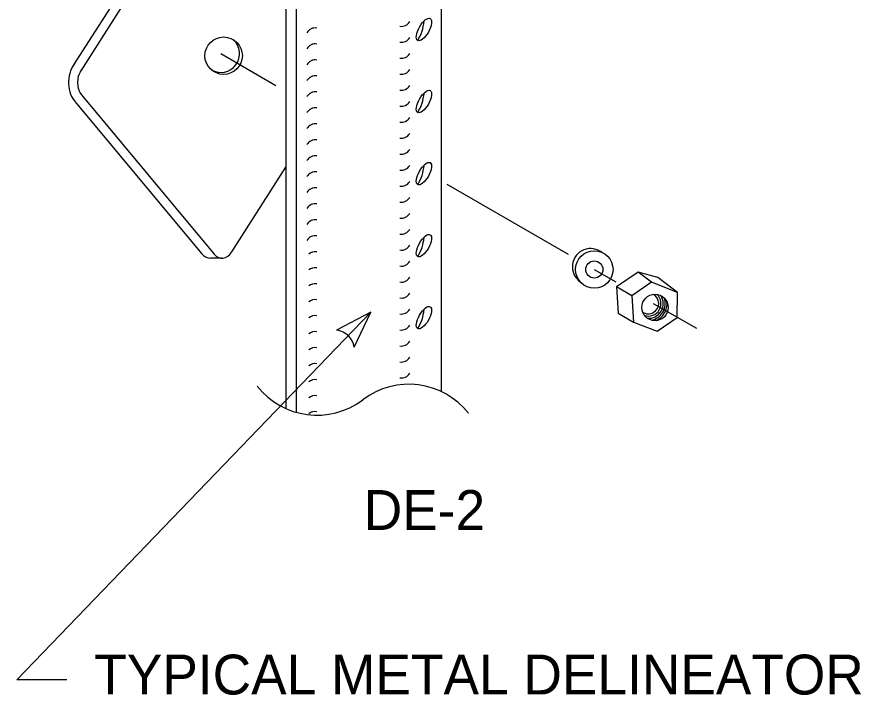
# Model space of a CAD drawing. Extents: x -0.14 to 2.7, y -0.05 to 1.78.
# Drawn here: x 0.5622 to 0.7392, y 1.3134 to 1.4552 of the extents above; entities that cross this region are included whole.
import ezdxf

# ---------------------------------------------------------------- set-up
doc = ezdxf.new("R2010")
doc.units = 0
doc.layers.add('CT_CSHT_GeneralLabel', color=7, linetype='Continuous')

msp = doc.modelspace()

# ---------------------------------------------------------------- linework, layer by layer
at = {"layer": 'CT_CSHT_GeneralLabel'}
for p, q in [((0.6509403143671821, 1.5261712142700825), (0.6509403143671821, 1.3768578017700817)), ((0.6184386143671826, 1.5115208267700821), (0.6184386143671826, 1.3733004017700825)), ((0.6206105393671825, 1.5115208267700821), (0.6206105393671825, 1.3725139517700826)), ((0.5988637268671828, 1.4840998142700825), (0.5740299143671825, 1.4451337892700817)), ((0.6010852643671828, 1.4840226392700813), (0.5755458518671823, 1.4439449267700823)), ((0.604841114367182, 1.4475023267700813), (0.6163475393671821, 1.4408560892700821)), ((0.5757002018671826, 1.4388715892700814), (0.6034501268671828, 1.4055742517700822)), ((0.5743257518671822, 1.4374622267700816), (0.600782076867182, 1.4057120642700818)), ((0.607132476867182, 1.4060428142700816), (0.6184386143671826, 1.4237875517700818)), ((0.6776079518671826, 1.4054823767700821), (0.652197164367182, 1.4201566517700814)), ((0.6050634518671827, 1.4047124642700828), (0.602720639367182, 1.404752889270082)), ((0.6829863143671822, 1.402378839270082), (0.6874845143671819, 1.3997806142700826)), ((0.6921921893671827, 1.4018239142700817), (0.6876076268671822, 1.398746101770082)), ((0.6962493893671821, 1.4006865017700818), (0.6921921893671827, 1.4018239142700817)), ((0.6949337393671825, 1.3997218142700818), (0.6921921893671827, 1.4018239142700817)), ((0.700367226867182, 1.3975407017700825), (0.6962493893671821, 1.4006865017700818)), ((0.6876076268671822, 1.398746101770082), (0.6879824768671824, 1.3932354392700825)), ((0.6908250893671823, 1.3968920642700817), (0.6876076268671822, 1.398746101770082)), ((0.704398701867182, 1.3900124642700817), (0.6954004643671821, 1.3952070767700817)), ((0.6362552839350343, 1.3934313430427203), (0.6290729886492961, 1.389674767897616)), ((0.6327633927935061, 1.386116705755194), (0.6362552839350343, 1.3934313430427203)), ((0.6879824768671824, 1.3932354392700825), (0.6911962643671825, 1.3913795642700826)), ((0.6327633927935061, 1.386116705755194), (0.6327633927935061, 1.386116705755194))]:
    msp.add_line(p, q, dxfattribs=at)
msp.add_lwpolyline([(0.6949337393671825, 1.3997218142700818), (0.6908250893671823, 1.3968920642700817), (0.6911962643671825, 1.3913795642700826), (0.6961299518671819, 1.3895108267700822), (0.7003415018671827, 1.3923387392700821), (0.700367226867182, 1.3975407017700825)], close=True, dxfattribs=at)
msp.add_lwpolyline([(0.572589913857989, 1.3165938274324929), (0.5621732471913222, 1.3165938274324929), (0.6362552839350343, 1.3934313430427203)], dxfattribs=at)
for centre, radius in [((0.6054260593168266, 1.4470713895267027), 0.003915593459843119), ((0.6829787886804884, 1.4023818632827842), 0.003920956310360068), ((0.6829789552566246, 1.4023819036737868), 0.0017902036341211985), ((0.6956814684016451, 1.3944483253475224), 0.0027620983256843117)]:
    msp.add_circle(centre, radius, dxfattribs=at)
for centre, radius, start, end in [((0.6426365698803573, 1.4552172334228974), 0.0020051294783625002, 260.31415833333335, 329.9999916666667), ((0.6383669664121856, 1.4550231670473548), 0.009025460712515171, 328.10828055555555, 355.1480833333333), ((0.6245738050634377, 1.4508792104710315), 0.0020051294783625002, 80.42088888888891, 149.99999444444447), ((0.604841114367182, 1.4475023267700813), 0.003915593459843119, 238.94371772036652, 48.29707947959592), ((0.6426365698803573, 1.4518753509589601), 0.0020051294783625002, 260.31415833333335, 329.9999916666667), ((0.6245738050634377, 1.4475373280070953), 0.0020051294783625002, 80.42088888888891, 149.99999444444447), ((0.6426365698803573, 1.448533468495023), 0.0020051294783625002, 260.31415833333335, 329.9999916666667), ((0.6245738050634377, 1.444195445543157), 0.0020051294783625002, 80.42088888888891, 149.99999444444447), ((0.6426365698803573, 1.4451915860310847), 0.0020051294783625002, 260.31415833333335, 329.9999916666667), ((0.6245738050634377, 1.4408535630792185), 0.0020051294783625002, 80.42088888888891, 149.99999444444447), ((0.6245738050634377, 1.4375116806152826), 0.0020051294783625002, 80.42088888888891, 149.99999444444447), ((0.6426365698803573, 1.4418497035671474), 0.0020051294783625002, 260.31415833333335, 329.9999916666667), ((0.6383669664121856, 1.4399606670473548), 0.009025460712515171, 328.10828055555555, 355.1480833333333), ((0.6245738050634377, 1.4341697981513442), 0.0020051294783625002, 80.42088888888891, 149.99999444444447), ((0.6426365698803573, 1.4385078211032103), 0.0020051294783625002, 260.31415833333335, 329.9999916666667), ((0.6426365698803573, 1.4351659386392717), 0.0020051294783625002, 260.31415833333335, 329.9999916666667), ((0.6245738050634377, 1.430827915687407), 0.0020051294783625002, 80.42088888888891, 149.99999444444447), ((0.6426365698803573, 1.4318240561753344), 0.0020051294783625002, 260.31415833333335, 329.9999916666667), ((0.6245738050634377, 1.42748603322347), 0.0020051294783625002, 80.42088888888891, 149.99999444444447), ((0.6426365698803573, 1.428482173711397), 0.0020051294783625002, 260.31415833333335, 329.9999916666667), ((0.6245738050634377, 1.4241441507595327), 0.0020051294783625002, 80.42088888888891, 149.99999444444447), ((0.6426365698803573, 1.42514029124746), 0.0020051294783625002, 260.31415833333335, 329.9999916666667), ((0.6383669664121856, 1.4248981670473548), 0.009025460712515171, 328.10828055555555, 355.1480833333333), ((0.6245738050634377, 1.4208022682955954), 0.0020051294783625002, 80.42088888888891, 149.99999444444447), ((0.6426365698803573, 1.4217984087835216), 0.0020051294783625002, 260.31415833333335, 329.9999916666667), ((0.6245738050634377, 1.417460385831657), 0.0020051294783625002, 80.42088888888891, 149.99999444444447), ((0.6426365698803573, 1.4184565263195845), 0.0020051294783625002, 260.31415833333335, 329.9999916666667), ((0.6245738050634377, 1.41411850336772), 0.0020051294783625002, 80.42088888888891, 149.99999444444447), ((0.6426365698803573, 1.4151146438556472), 0.0020051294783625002, 260.31415833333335, 329.9999916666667), ((0.6245738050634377, 1.4107766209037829), 0.0020051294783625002, 80.42088888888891, 149.99999444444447), ((0.6245738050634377, 1.4074347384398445), 0.0020051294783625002, 80.42088888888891, 149.99999444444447), ((0.6426365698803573, 1.4117727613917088), 0.0020051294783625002, 260.31415833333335, 329.9999916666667), ((0.6383669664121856, 1.409835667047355), 0.009025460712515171, 328.10828055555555, 355.1480833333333), ((0.6245738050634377, 1.4040928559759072), 0.0020051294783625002, 80.42088888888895, 130.60729166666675), ((0.6426365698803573, 1.4084308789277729), 0.0020051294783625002, 260.31415833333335, 329.9999916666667), ((0.682201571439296, 1.402947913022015), 0.0038036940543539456, 49.63861111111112, 235.0894777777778), ((0.6426365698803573, 1.4050889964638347), 0.0020051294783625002, 260.31415833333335, 329.9999916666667), ((0.6245738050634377, 1.40075097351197), 0.0020051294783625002, 80.42088888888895, 130.60729166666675), ((0.6426365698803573, 1.4017471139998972), 0.0020051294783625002, 260.31415833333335, 329.9999916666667), ((0.6245738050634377, 1.3974090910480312), 0.0020051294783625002, 80.42088888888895, 130.60729166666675), ((0.6426365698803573, 1.39840523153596), 0.0020051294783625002, 260.31415833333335, 329.9999916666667), ((0.6943079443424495, 1.3952543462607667), 0.002153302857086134, 235.7802416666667, 63.40862500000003), ((0.6943079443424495, 1.3952543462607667), 0.0026252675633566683, 252.0190777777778, 47.16979722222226), ((0.6943079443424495, 1.3952543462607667), 0.003091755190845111, 265.5043, 32.62691944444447), ((0.6245738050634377, 1.3940672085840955), 0.0020051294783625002, 80.42088888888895, 130.60729166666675), ((0.6943079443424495, 1.3952543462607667), 0.003507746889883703, 279.7938638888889, 19.395000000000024), ((0.6943079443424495, 1.3952543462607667), 0.0038982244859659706, 294.0540138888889, 5.134858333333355), ((0.6426365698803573, 1.395063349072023), 0.0020051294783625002, 260.31415833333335, 329.9999916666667), ((0.6383669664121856, 1.3947731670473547), 0.009025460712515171, 328.10828055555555, 355.1480833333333), ((0.6245738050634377, 1.390725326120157), 0.0020051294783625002, 80.42088888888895, 130.60729166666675), ((0.6426365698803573, 1.3917214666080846), 0.0020051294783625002, 260.31415833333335, 329.9999916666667), ((0.6245738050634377, 1.3873834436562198), 0.0020051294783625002, 80.42088888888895, 130.60729166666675), ((0.6286085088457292, 1.3854994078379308), 0.004200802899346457, 8.445169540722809, 83.64680009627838), ((0.6426365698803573, 1.3883795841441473), 0.0020051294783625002, 260.31415833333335, 329.9999916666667), ((0.6245738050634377, 1.3840415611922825), 0.0020051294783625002, 80.42088888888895, 130.60729166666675), ((0.6426365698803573, 1.3850377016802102), 0.0020051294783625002, 260.31415833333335, 329.9999916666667), ((0.6245738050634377, 1.3806996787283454), 0.0020051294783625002, 80.42088888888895, 130.60729166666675), ((0.6245738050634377, 1.377357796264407), 0.0020051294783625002, 80.42088888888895, 130.60729166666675), ((0.6426365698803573, 1.3816958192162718), 0.0020051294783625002, 260.31415833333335, 329.9999916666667), ((0.624930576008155, 1.3877970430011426), 0.015882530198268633, 218.15082500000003, 307.21875833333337), ((0.6441439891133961, 1.3625015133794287), 0.015882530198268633, 38.150825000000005, 127.21875833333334), ((0.6245738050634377, 1.3740159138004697), 0.0020051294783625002, 80.42088888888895, 130.60729166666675), ((0.6245738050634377, 1.3706740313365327), 0.0020051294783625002, 80.42088888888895, 130.60729166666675)]:
    msp.add_arc(centre, radius, start, end, dxfattribs=at)
for centre in [(0.6473320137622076, 1.4525494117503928), (0.6473320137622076, 1.4374869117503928), (0.6473320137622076, 1.422424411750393), (0.6473320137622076, 1.407361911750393), (0.6473320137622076, 1.3922994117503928)]:
    msp.add_ellipse(centre, major_axis=(0.00130166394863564, 0.002294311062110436), ratio=0.40310763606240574, dxfattribs=at)
for centre, major_axis, ratio, start_param, end_param in [((0.5774665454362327, 1.4416450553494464), (0.00037701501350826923, 0.005684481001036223), 0.7867206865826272, 0.9220534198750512, 2.492942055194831), ((0.5774665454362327, 1.4416450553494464), (0.00027460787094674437, 0.003596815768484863), 0.7207785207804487, 0.9324204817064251, 2.503309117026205), ((0.6052139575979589, 1.4083444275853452), (-0.0002746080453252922, -0.0035968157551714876), 0.720778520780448, 5.644631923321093, 7.215486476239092), ((0.6027732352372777, 1.4077576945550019), (-5.2491939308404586e-05, -0.0030072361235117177), 0.8999999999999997, 5.476378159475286, 6.283185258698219)]:
    msp.add_ellipse(centre, major_axis=major_axis, ratio=ratio, start_param=start_param, end_param=end_param, dxfattribs=at)

# ---------------------------------------------------------------- texts
for s, p in [('DE-2', (0.6347487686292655, 1.3479231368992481)), ('TYPICAL METAL DELINEATOR POST', (0.5783611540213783, 1.3135200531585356))]:
    msp.add_text(s, height=0.008333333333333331, dxfattribs=at).set_placement(p)

doc.saveas('drawing.dxf')
